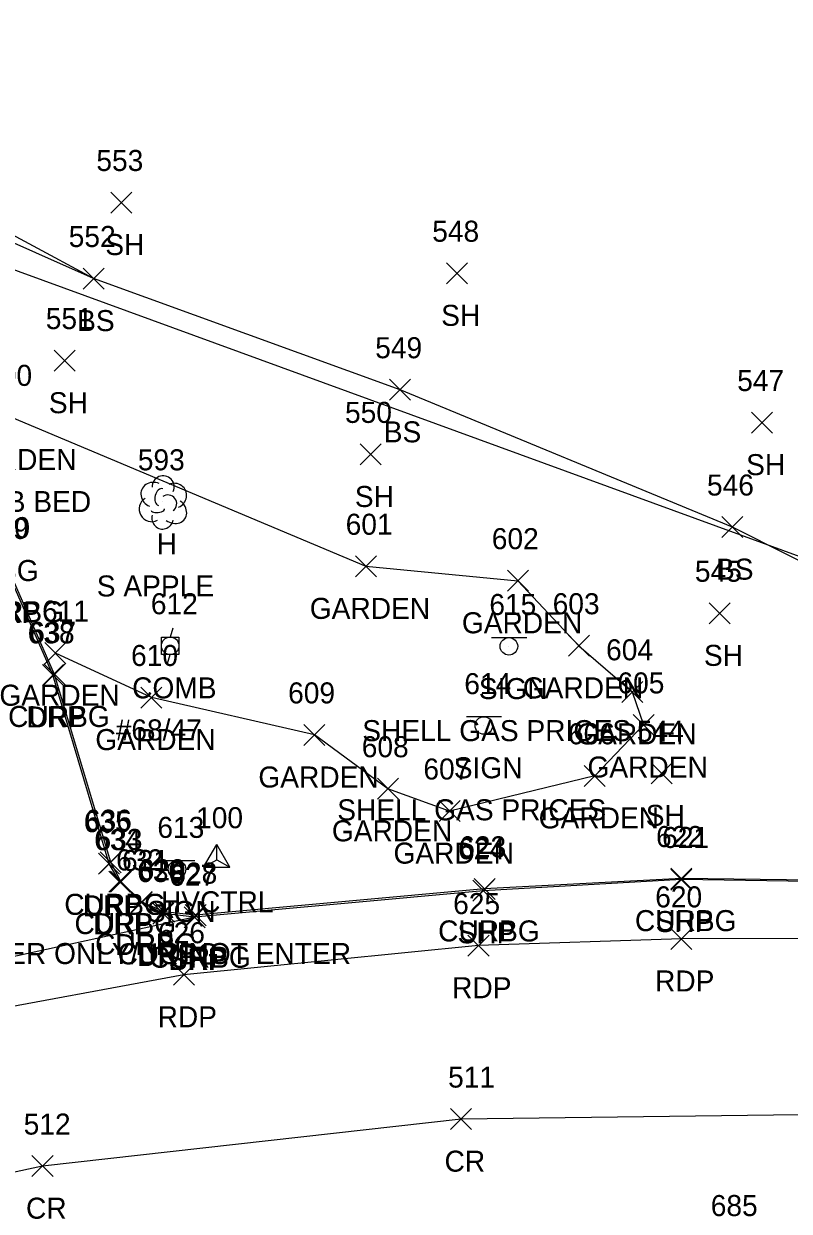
# Model space of a CAD drawing. Extents: x 1678863 to 1683592, y 407783 to 418211.
# Drawn here: x 1681603.1 to 1681675.9, y 417748.8 to 417861.7 of the extents above; entities that cross this region are included whole.
import ezdxf

# ---------------------------------------------------------------- set-up
doc = ezdxf.new("R2010")
doc.units = 0
for name, color, linetype in [('C_A', 7, 'Continuous'), ('C_I', 7, 'Continuous'), ('CPSM', 7, 'Continuous'), ('DCP', 7, 'Continuous'), ('L_A', 7, 'Continuous'), ('L_C', 7, 'Continuous'), ('L_I', 7, 'Continuous'), ('L_TIC', 7, 'Continuous'), ('LAPB', 7, 'Continuous'), ('LELB', 7, 'Continuous'), ('LTD', 7, 'Continuous'), ('P_A', 7, 'Continuous'), ('P_I', 7, 'Continuous'), ('P_TIC', 7, 'Continuous'), ('PET', 7, 'Continuous'), ('PRC', 7, 'Continuous'), ('PSP', 7, 'Continuous'), ('R_A', 7, 'Continuous'), ('R_I', 7, 'Continuous'), ('R_TIC', 7, 'Continuous'), ('RC', 7, 'Continuous'), ('RDP', 7, 'Continuous'), ('S_A', 7, 'Continuous'), ('S_C', 7, 'Continuous'), ('S_I', 7, 'Continuous'), ('SSGN', 7, 'Continuous'), ('U_A', 7, 'Continuous'), ('U_C', 7, 'Continuous'), ('U_I', 7, 'Continuous'), ('UP', 7, 'Continuous')]:
    doc.layers.add(name, color=color, linetype=linetype)

msp = doc.modelspace()

# ---------------------------------------------------------------- linework, layer by layer
at = {"layer": 'CPSM'}
for p, q in [((1681620.24, 417781.5), (1681621.49, 417783.66)), ((1681622.74, 417781.5), (1681621.49, 417783.66)), ((1681621.49, 417782.22), (1681621.49, 417783.66)), ((1681620.24, 417781.5), (1681621.49, 417782.22)), ((1681621.49, 417782.22), (1681621.49, 417782.22)), ((1681621.49, 417782.22), (1681622.74, 417781.5)), ((1681620.24, 417781.5), (1681622.74, 417781.5))]:
    msp.add_line(p, q, dxfattribs=at)
at = {"layer": 'DCP'}
msp.add_lwpolyline([(1681807.98, 417763.2), (1681579.97, 417846.45)], dxfattribs=at)
at = {"layer": 'L_TIC'}
for points in [[(1681611.41, 417843.73), (1681613.41, 417845.73)], [(1681613.41, 417843.73), (1681611.41, 417845.73)], [(1681608.78, 417836.5), (1681610.78, 417838.5)], [(1681610.78, 417836.5), (1681608.78, 417838.5)], [(1681608.78, 417836.5), (1681610.78, 417838.5)], [(1681610.78, 417836.5), (1681608.78, 417838.5)], [(1681643.34, 417837), (1681645.34, 417839)], [(1681645.34, 417837), (1681643.34, 417839)], [(1681606.04, 417828.69), (1681608.04, 417830.69)], [(1681608.04, 417828.69), (1681606.04, 417830.69)], [(1681637.93, 417825.92), (1681639.93, 417827.92)], [(1681639.93, 417825.92), (1681637.93, 417827.92)], [(1681672.33, 417822.8), (1681674.33, 417824.8)], [(1681674.33, 417822.8), (1681672.33, 417824.8)], [(1681635.14, 417819.77), (1681637.14, 417821.77)], [(1681637.14, 417819.77), (1681635.14, 417821.77)], [(1681669.52, 417812.86), (1681671.52, 417814.86)], [(1681671.52, 417812.86), (1681669.52, 417814.86)], [(1681634.67, 417809.13), (1681636.67, 417811.13)], [(1681636.67, 417809.13), (1681634.67, 417811.13)], [(1681649.13, 417807.76), (1681651.13, 417809.76)], [(1681651.13, 417807.76), (1681649.13, 417809.76)], [(1681668.32, 417804.66), (1681670.32, 417806.66)], [(1681670.32, 417804.66), (1681668.32, 417806.66)], [(1681654.92, 417801.57), (1681656.92, 417803.57)], [(1681656.92, 417801.57), (1681654.92, 417803.57)], [(1681605.16, 417800.87), (1681607.16, 417802.87)], [(1681607.16, 417800.87), (1681605.16, 417802.87)], [(1681660, 417797.19), (1681662, 417799.19)], [(1681662, 417797.19), (1681660, 417799.19)], [(1681614.28, 417796.65), (1681616.28, 417798.65)], [(1681616.28, 417796.65), (1681614.28, 417798.65)], [(1681661.07, 417794.04), (1681663.07, 417796.04)], [(1681663.07, 417794.04), (1681661.07, 417796.04)], [(1681629.78, 417793.09), (1681631.78, 417795.09)], [(1681631.78, 417793.09), (1681629.78, 417795.09)], [(1681656.43, 417789.2), (1681658.43, 417791.2)], [(1681658.43, 417789.2), (1681656.43, 417791.2)], [(1681662.79, 417789.44), (1681664.79, 417791.44)], [(1681664.79, 417789.44), (1681662.79, 417791.44)], [(1681636.77, 417787.97), (1681638.77, 417789.97)], [(1681638.77, 417787.97), (1681636.77, 417789.97)], [(1681642.63, 417785.85), (1681644.63, 417787.85)], [(1681644.63, 417785.85), (1681642.63, 417787.85)]]:
    msp.add_lwpolyline(points, dxfattribs=at)
at = {"layer": 'LAPB'}
msp.add_lwpolyline([(1681589.7, 417828.33), (1681602.05, 417824.29), (1681635.67, 417810.13), (1681650.13, 417808.76), (1681655.92, 417802.57), (1681661, 417798.19), (1681662.07, 417795.04), (1681657.43, 417790.2), (1681643.63, 417786.85), (1681637.77, 417788.97), (1681630.78, 417794.09), (1681615.28, 417797.65), (1681606.16, 417801.87)], dxfattribs=at)
at = {"layer": 'LELB'}
for points in [[(1681808.38, 417761.41), (1681772.94, 417773.89), (1681739.45, 417784.06), (1681717.85, 417793.04), (1681686.59, 417805.76), (1681670.52, 417813.86), (1681638.93, 417826.92), (1681609.78, 417837.5), (1681593.01, 417844.94), (1681556.32, 417860.63), (1681530.21, 417868.9), (1681501.4, 417878.99), (1681480.67, 417886.23), (1681463.08, 417899.46), (1681453.92, 417912.7)], [(1681609.78, 417837.5), (1681591.41, 417847.4), (1681556.32, 417860.63)]]:
    msp.add_lwpolyline(points, dxfattribs=at)
at = {"layer": 'LTD'}
msp.add_line((1681616.36, 417816.26), (1681616.36, 417816.26), dxfattribs=at)
msp.add_line((1681616.36, 417816.26), (1681616.36, 417816.26), dxfattribs=at)
msp.add_arc((1681616.4, 417817.69), 1.05, 335.5272, 180.9563, dxfattribs=at)
for centre, major_axis, ratio, start_param, end_param in [((1681615.57, 417816.92), (1.21, -0.51), 0.895232, 1.570796, 4.712389), ((1681617.4, 417816.84), (-1.14, -0.48), 0.949671, 1.570796, 4.712389), ((1681616.15, 417816.72), (-0.208, -0.792), 0.645439, 3.141593, 6.283185), ((1681616.86, 417816.09), (-0.5, 0.667), 0.989748, 3.141593, 6.283185), ((1681615.27, 417815.55), (0.58, -1.04), 0.959034, 3.141593, 6.283185), ((1681617.36, 417815.42), (-1.09, 0.79), 0.841452, 1.570796, 4.712389), ((1681616.36, 417814.76), (0.26, 1.06), 0.942809, 1.570796, 4.712389), ((1681615.9, 417815.51), (-0.625, -0.083), 0.423636, 0, 3.141593)]:
    msp.add_ellipse(centre, major_axis=major_axis, ratio=ratio, start_param=start_param, end_param=end_param, dxfattribs=at)
at = {"layer": 'P_TIC'}
for points in [[(1681664.67, 417779.34), (1681666.67, 417781.34)], [(1681666.67, 417779.34), (1681664.67, 417781.34)], [(1681645.85, 417778.27), (1681647.85, 417780.27)], [(1681647.85, 417778.27), (1681645.85, 417780.27)], [(1681618.39, 417775.75), (1681620.39, 417777.75)], [(1681620.39, 417775.75), (1681618.39, 417777.75)], [(1681664.67, 417773.69), (1681666.67, 417775.69)], [(1681666.67, 417773.69), (1681664.67, 417775.69)], [(1681645.38, 417773.05), (1681647.38, 417775.05)], [(1681647.38, 417773.05), (1681645.38, 417775.05)], [(1681617.38, 417770.28), (1681619.38, 417772.28)], [(1681619.38, 417770.28), (1681617.38, 417772.28)], [(1681643.72, 417756.55), (1681645.72, 417758.55)], [(1681645.72, 417756.55), (1681643.72, 417758.55)], [(1681603.93, 417752.08), (1681605.93, 417754.08)], [(1681605.93, 417752.08), (1681603.93, 417754.08)]]:
    msp.add_lwpolyline(points, dxfattribs=at)
at = {"layer": 'PET'}
msp.add_lwpolyline([(1681688.07, 417774.74), (1681665.67, 417774.69), (1681646.38, 417774.05), (1681618.38, 417771.28), (1681597.44, 417767.4), (1681571, 417761.82), (1681551.36, 417756.57), (1681536.99, 417751.33), (1681520.34, 417745.37), (1681501.18, 417737.2)], dxfattribs=at)
at = {"layer": 'PRC'}
msp.add_lwpolyline([(1681689.28, 417758.12), (1681644.72, 417757.55), (1681604.93, 417753.08), (1681563.91, 417744.25), (1681526.24, 417731.47), (1681503.63, 417720.81), (1681486.3, 417712.13), (1681462.37, 417697.78), (1681439.98, 417682.26), (1681419.65, 417665.87), (1681392.79, 417639.13), (1681372.86, 417615.48), (1681356.04, 417592.08), (1681338.97, 417563.39), (1681323.96, 417530.56), (1681315.3, 417508.31), (1681305.4, 417475.77), (1681297.72, 417448.3), (1681287.9, 417409.62), (1681275.84, 417355.43), (1681267.02, 417318.48), (1681254.6, 417262.47)], dxfattribs=at)
at = {"layer": 'PSP'}
msp.add_lwpolyline([(1681807.43, 417757.08), (1681770.66, 417766.63), (1681736.19, 417773.98), (1681713.28, 417776.61), (1681712.2, 417778.13), (1681688.03, 417779.99), (1681665.67, 417780.34), (1681646.85, 417779.27), (1681619.39, 417776.75), (1681597, 417771.87), (1681570.22, 417766.76), (1681550.36, 417761.29), (1681535.13, 417756.57), (1681519.66, 417750.5), (1681498.64, 417740.7), (1681474.32, 417729.71), (1681451.83, 417714.81), (1681430.73, 417700.08), (1681426.98, 417697.92), (1681424.47, 417696.86), (1681417.87, 417695.44)], dxfattribs=at)
at = {"layer": 'R_TIC'}
for points in [[(1681604.92, 417798.8), (1681606.92, 417800.8)], [(1681606.92, 417798.8), (1681604.92, 417800.8)], [(1681605.07, 417798.85), (1681607.07, 417800.85)], [(1681607.07, 417798.85), (1681605.07, 417800.85)], [(1681610.26, 417780.84), (1681612.26, 417782.84)], [(1681612.26, 417780.84), (1681610.26, 417782.84)], [(1681610.42, 417780.98), (1681612.42, 417782.98)], [(1681612.42, 417780.98), (1681610.42, 417782.98)], [(1681611.25, 417779.14), (1681613.25, 417781.14)], [(1681613.25, 417779.14), (1681611.25, 417781.14)], [(1681611.38, 417779.15), (1681613.38, 417781.15)], [(1681613.38, 417779.15), (1681611.38, 417781.15)], [(1681664.67, 417779.43), (1681666.67, 417781.43)], [(1681666.67, 417779.43), (1681664.67, 417781.43)], [(1681645.96, 417778.45), (1681647.96, 417780.45)], [(1681647.96, 417778.45), (1681645.96, 417780.45)], [(1681613.34, 417777.21), (1681615.34, 417779.21)], [(1681615.34, 417777.21), (1681613.34, 417779.21)], [(1681613.34, 417777.15), (1681615.34, 417779.15)], [(1681615.34, 417777.15), (1681613.34, 417779.15)], [(1681615.42, 417776.1), (1681617.42, 417778.1)], [(1681617.42, 417776.1), (1681615.42, 417778.1)], [(1681615.48, 417776.27), (1681617.48, 417778.27)], [(1681617.48, 417776.27), (1681615.48, 417778.27)], [(1681618.39, 417775.75), (1681620.39, 417777.75)], [(1681620.39, 417775.75), (1681618.39, 417777.75)], [(1681618.49, 417775.95), (1681620.49, 417777.95)], [(1681620.49, 417775.95), (1681618.49, 417777.95)]]:
    msp.add_lwpolyline(points, dxfattribs=at)
at = {"layer": 'RC'}
msp.add_lwpolyline([(1681688.1, 417780.14), (1681665.67, 417780.43), (1681646.96, 417779.45), (1681619.49, 417776.95), (1681616.48, 417777.27), (1681614.34, 417778.21), (1681612.38, 417780.15), (1681611.42, 417781.98), (1681606.07, 417799.85), (1681601.73, 417809.81), (1681599.33, 417813.73), (1681596.63, 417817), (1681591.79, 417820.59), (1681580.5, 417827.23), (1681568.54, 417833.47), (1681557.52, 417838.06), (1681541.71, 417843.71), (1681528.62, 417847.88), (1681500.36, 417854.63)], dxfattribs=at)
at = {"layer": 'RDP'}
msp.add_lwpolyline([(1681619.39, 417776.75), (1681616.42, 417777.1), (1681614.34, 417778.15), (1681612.25, 417780.14), (1681611.26, 417781.84), (1681605.92, 417799.8), (1681601.57, 417809.73), (1681599.21, 417813.67), (1681596.52, 417816.87), (1681591.74, 417820.5), (1681580.28, 417827.13), (1681568.42, 417833.26), (1681557.53, 417837.93), (1681541.57, 417843.58), (1681528.67, 417847.68), (1681500.37, 417854.53)], dxfattribs=at)
at = {"layer": 'SSGN'}
for p, q in [((1681647.63, 417803.35), (1681650.96, 417803.35)), ((1681649.27, 417802.52), (1681649.27, 417802.52)), ((1681645.24, 417795.83), (1681648.57, 417795.83)), ((1681646.89, 417794.99), (1681646.89, 417794.99)), ((1681616.07, 417782.15), (1681619.4, 417782.15)), ((1681617.72, 417781.32), (1681617.72, 417781.32))]:
    msp.add_line(p, q, dxfattribs=at)
for centre in [(1681649.27, 417802.52), (1681646.89, 417794.99), (1681617.72, 417781.32)]:
    msp.add_circle(centre, 0.833, dxfattribs=at)
at = {"layer": 'UP'}
for p, q in [((1681617.32, 417804.24), (1681617.07, 417803.4)), ((1681616.23, 417801.74), (1681616.23, 417803.4)), ((1681616.23, 417803.4), (1681617.9, 417803.4)), ((1681617.07, 417802.57), (1681617.07, 417802.57)), ((1681617.9, 417803.4), (1681617.9, 417801.74)), ((1681617.9, 417801.74), (1681616.23, 417801.74)), ((1681616.82, 417800.9), (1681617.07, 417801.74))]:
    msp.add_line(p, q, dxfattribs=at)
msp.add_circle((1681617.07, 417802.57), 0.833, dxfattribs=at)

# ---------------------------------------------------------------- texts
at = {"layer": 'C_A'}
msp.add_text('HVCTRL', height=2, dxfattribs=at).set_placement((1681616.19, 417777.22))
at = {"layer": 'C_I'}
msp.add_text('100', height=2, dxfattribs=at).set_placement((1681619.53, 417785.22))
at = {"layer": 'L_A'}
for s, p in [('SH', (1681610.9, 417839.73)), ('BS', (1681608.22, 417832.5)), ('BS', (1681608.22, 417832.5)), ('SH', (1681642.83, 417833)), ('SH', (1681605.53, 417824.69)), ('BS', (1681637.37, 417821.92)), ('GARDEN', (1681596.72, 417819.29)), ('SH', (1681671.82, 417818.8)), ('SH', (1681634.62, 417815.77)), ('H', (1681615.79, 417811.26)), ('BS', (1681668.96, 417808.86)), ('GARDEN', (1681630.34, 417805.13)), ('GARDEN', (1681644.8, 417803.76)), ('SH', (1681667.81, 417800.66)), ('GARDEN', (1681600.83, 417796.87)), ('GARDEN', (1681650.59, 417797.57)), ('GARDEN', (1681609.95, 417792.65)), ('GARDEN', (1681655.67, 417793.19)), ('GARDEN', (1681625.45, 417789.09)), ('GARDEN', (1681656.74, 417790.04)), ('GARDEN', (1681652.1, 417785.2)), ('SH', (1681662.28, 417785.44)), ('GARDEN', (1681632.44, 417783.97)), ('GARDEN', (1681638.3, 417781.85))]:
    msp.add_text(s, height=2, dxfattribs=at).set_placement(p)
at = {"layer": 'L_C'}
for s, p in [('SHRUB BED', (1681593.95, 417815.29)), ('S APPLE', (1681610.09, 417807.26))]:
    msp.add_text(s, height=2, dxfattribs=at).set_placement(p)
at = {"layer": 'L_I'}
for s, p in [('553', (1681610.05, 417847.73)), ('548', (1681641.98, 417841)), ('552', (1681607.42, 417840.5)), ('552', (1681607.42, 417840.5)), ('551', (1681605.24, 417832.69)), ('549', (1681636.56, 417829.92)), ('600', (1681599.48, 417827.29)), ('547', (1681670.97, 417826.8)), ('550', (1681633.69, 417823.77)), ('593', (1681613.99, 417819.26)), ('546', (1681668.1, 417816.86)), ('601', (1681633.75, 417813.13)), ('602', (1681647.64, 417811.76)), ('545', (1681666.95, 417808.66)), ('611', (1681604.89, 417804.87)), ('603', (1681653.43, 417805.57)), ('610', (1681613.35, 417800.65)), ('604', (1681658.51, 417801.19)), ('605', (1681659.59, 417798.04)), ('609', (1681628.28, 417797.09)), ('606', (1681654.89, 417793.2)), ('544', (1681661.43, 417793.44)), ('608', (1681635.28, 417791.97)), ('607', (1681641.14, 417789.85))]:
    msp.add_text(s, height=2, dxfattribs=at).set_placement(p)
at = {"layer": 'P_A'}
for s, p in [('SHP', (1681663.21, 417775.34)), ('SHP', (1681644.38, 417774.27)), ('SHP', (1681616.93, 417771.75)), ('RDP', (1681643.87, 417769.05)), ('RDP', (1681663.16, 417769.69)), ('RDP', (1681615.87, 417766.28)), ('CR', (1681643.15, 417752.55)), ('CR', (1681603.36, 417748.08))]:
    msp.add_text(s, height=2, dxfattribs=at).set_placement(p)
at = {"layer": 'P_I'}
for s, p in [('621', (1681663.83, 417783.34)), ('624', (1681644.44, 417782.27)), ('627', (1681616.98, 417779.75)), ('620', (1681663.18, 417777.69)), ('625', (1681643.97, 417777.05)), ('626', (1681615.91, 417774.28)), ('511', (1681643.49, 417760.55)), ('512', (1681603.14, 417756.08)), ('685', (1681668.46, 417748.33))]:
    msp.add_text(s, height=2, dxfattribs=at).set_placement(p)
at = {"layer": 'R_A'}
for s, p in [('CURBG', (1681594.91, 417808.73)), ('CURBG', (1681597.31, 417804.81)), ('DRP', (1681599.06, 417804.73)), ('CURBG', (1681601.66, 417794.85)), ('DRP', (1681603.41, 417794.8)), ('CURBG', (1681607, 417776.98)), ('DRP', (1681608.75, 417776.84)), ('CURBG', (1681661.25, 417775.43)), ('CURBG', (1681607.97, 417775.15)), ('DRP', (1681609.74, 417775.14)), ('CURBG', (1681642.54, 417774.45)), ('CURBG', (1681609.93, 417773.21)), ('DRP', (1681611.82, 417773.15)), ('CURBG', (1681612.07, 417772.27)), ('DRP', (1681613.91, 417772.1)), ('CURBG', (1681615.07, 417771.95)), ('DRP', (1681616.88, 417771.75))]:
    msp.add_text(s, height=2, dxfattribs=at).set_placement(p)
at = {"layer": 'R_I'}
for s, p in [('769', (1681599.16, 417812.73)), ('770', (1681599.28, 417812.81)), ('638', (1681603.52, 417802.8)), ('637', (1681603.67, 417802.85)), ('635', (1681608.85, 417784.84)), ('636', (1681608.96, 417784.98)), ('622', (1681663.26, 417783.43)), ('634', (1681609.84, 417783.14)), ('633', (1681609.97, 417783.15)), ('623', (1681644.55, 417782.45)), ('632', (1681611.93, 417781.21)), ('631', (1681612.49, 417781.15)), ('630', (1681613.93, 417780.1)), ('629', (1681614.07, 417780.27)), ('628', (1681617.08, 417779.95)), ('627', (1681616.98, 417779.75))]:
    msp.add_text(s, height=2, dxfattribs=at).set_placement(p)
at = {"layer": 'S_A'}
for p in [(1681646.41, 417797.5), (1681644.03, 417789.97), (1681614.85, 417776.3)]:
    msp.add_text('SIGN', height=2, dxfattribs=at).set_placement(p)
at = {"layer": 'S_C'}
for s, p in [('SHELL GAS PRICES', (1681635.33, 417793.5)), ('SHELL GAS PRICES', (1681632.95, 417785.97)), ('ENTER ONLY/DO NOT ENTER', (1681596.22, 417772.3))]:
    msp.add_text(s, height=2, dxfattribs=at).set_placement(p)
at = {"layer": 'S_I'}
for s, p in [('615', (1681647.41, 417805.5)), ('614', (1681645.03, 417797.97)), ('613', (1681615.85, 417784.3))]:
    msp.add_text(s, height=2, dxfattribs=at).set_placement(p)
at = {"layer": 'U_A'}
msp.add_text('COMB', height=2, dxfattribs=at).set_placement((1681613.45, 417797.57))
at = {"layer": 'U_C'}
msp.add_text('#68/47', height=2, dxfattribs=at).set_placement((1681611.89, 417793.57))
at = {"layer": 'U_I'}
msp.add_text('612', height=2, dxfattribs=at).set_placement((1681615.23, 417805.57))

doc.saveas('drawing.dxf')
